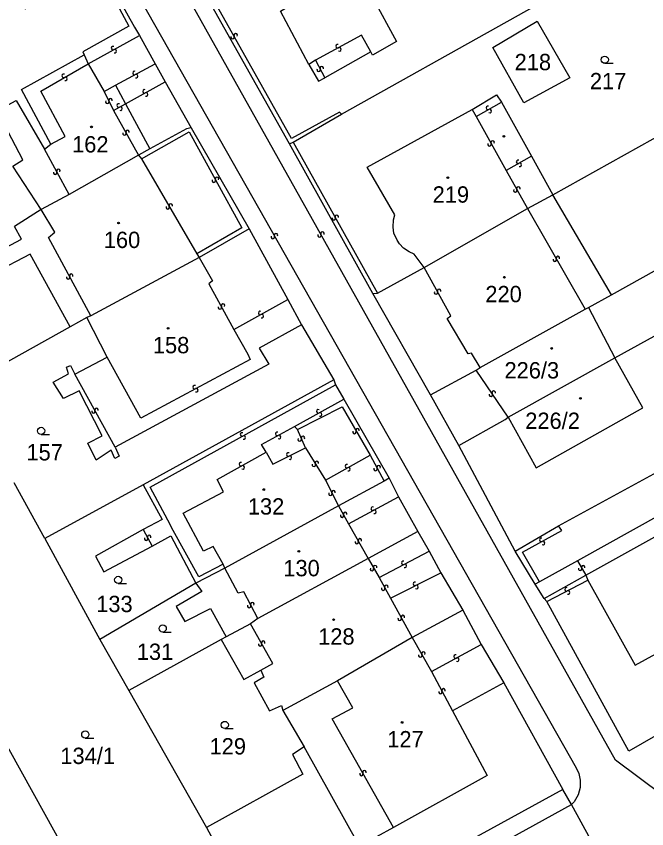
# Model space of a CAD drawing. Extents: x -600391 to -599491, y -1160176 to -1159402.
# Drawn here: x -600329.6 to -600264, y -1159832 to -1159747.5 of the extents above; entities that cross this region are included whole.
import ezdxf

# ---------------------------------------------------------------- set-up
doc = ezdxf.new("R2010")
doc.units = 0
for name, color, linetype in [('Level 1', 7, 'Continuous'), ('Level 13', 7, 'Continuous'), ('Level 3', 7, 'Continuous'), ('Level 4', 7, 'Continuous'), ('Level 5', 7, 'Continuous')]:
    doc.layers.add(name, color=color, linetype=linetype)

msp = doc.modelspace()

# ---------------------------------------------------------------- linework, layer by layer
at = {"layer": 'Level 1'}
for points in [[(-600299.17, -1159752.49), (-600302.11, -1159746.96), (-600301.17, -1159746.41), (-600303.61, -1159741.8), (-600292.85, -1159735.57), (-600288.77, -1159743.19), (-600292.56, -1159745.42), (-600290.03, -1159750.12), (-600292.55, -1159751.52), (-600292.72, -1159751.2)], [(-600295.75, -1159757.68), (-600261.29, -1159738.36)], [(-600301.19, -1159760.77), (-600313.32, -1159739.14)], [(-600320.77, -1159741.86), (-600320.81, -1159742.32), (-600317.3, -1159748.63), (-600316.77, -1159749.5)], [(-600280.02, -1159750.72), (-600275.38, -1159747.98), (-600271.99, -1159753.9), (-600276.77, -1159756.5), (-600280.02, -1159750.72)], [(-600316.77, -1159749.5), (-600315.17, -1159752.43)], [(-600292.72, -1159751.2), (-600297.48, -1159753.88)], [(-600326.01, -1159760.79), (-600329.08, -1159755.1), (-600322.55, -1159751.51)], [(-600322.55, -1159751.51), (-600322.12, -1159752.43)], [(-600322.12, -1159752.43), (-600320.45, -1159755.32)], [(-600315.17, -1159752.43), (-600314.12, -1159754.32)], [(-600299.17, -1159752.49), (-600298.16, -1159754.23), (-600297.48, -1159753.88)], [(-600320.45, -1159755.32), (-600319.27, -1159754.67)], [(-600319.27, -1159754.67), (-600318.23, -1159756.59)], [(-600314.12, -1159754.32), (-600311.4, -1159759.11)], [(-600273.75, -1159766.05), (-600252.87, -1159754.41)], [(-600327.03, -1159767.58), (-600329.98, -1159763.08), (-600328.92, -1159762.44), (-600331.62, -1159757.33), (-600329.63, -1159756.26), (-600326.67, -1159761.32)], [(-600282.17, -1159757.17), (-600279.61, -1159755.67), (-600279.11, -1159756.44)], [(-600318.23, -1159756.59), (-600315.71, -1159761.28)], [(-600287.15, -1159773.61), (-600288.19, -1159772.24), (-600288.73, -1159772), (-600289.31, -1159771.61), (-600289.72, -1159771.17), (-600289.98, -1159770.79), (-600290.3, -1159770.07), (-600290.39, -1159769.43), (-600290.35, -1159768.68), (-600290.22, -1159768.16), (-600293.08, -1159763.17), (-600282.17, -1159757.17)], [(-600279.11, -1159756.44), (-600275.97, -1159762.05)], [(-600300.8, -1159760.59), (-600295.75, -1159757.68)], [(-600311.4, -1159759.11), (-600311.9, -1159759.19), (-600315.71, -1159761.28)], [(-600311.4, -1159759.11), (-600305.38, -1159769.61)], [(-600301.19, -1159760.77), (-600300.8, -1159760.59)], [(-600326.67, -1159761.32), (-600326.01, -1159760.79)], [(-600315.71, -1159761.28), (-600316.89, -1159761.93)], [(-600292.5, -1159776.32), (-600301.19, -1159760.77)], [(-600316.89, -1159761.93), (-600324.12, -1159766.04)], [(-600275.97, -1159762.05), (-600273.75, -1159766.05)], [(-600267.66, -1159776.47), (-600247.31, -1159765.14)], [(-600324.12, -1159766.04), (-600327.03, -1159767.58)], [(-600276.4, -1159767.49), (-600273.75, -1159766.05)], [(-600267.66, -1159776.47), (-600273.75, -1159766.05)], [(-600327.03, -1159767.58), (-600329.78, -1159769.35)], [(-600287.15, -1159773.61), (-600276.4, -1159767.49)], [(-600324, -1159779.81), (-600328.15, -1159772.25), (-600331.92, -1159774.18), (-600332.83, -1159772.65), (-600329.08, -1159770.69), (-600329.78, -1159769.35)], [(-600305.38, -1159769.61), (-600310.58, -1159772.6)], [(-600305.38, -1159769.61), (-600301.33, -1159776.97)], [(-600267.31, -1159783.02), (-600244.51, -1159770.47)], [(-600310.58, -1159772.6), (-600321.85, -1159778.65)], [(-600292.02, -1159776.29), (-600287.15, -1159773.61)], [(-600292.5, -1159776.32), (-600292.02, -1159776.29)], [(-600286.5, -1159786.86), (-600292.5, -1159776.32)], [(-600270.06, -1159777.8), (-600267.66, -1159776.47)], [(-600301.33, -1159776.97), (-600299.92, -1159779.6)], [(-600281.32, -1159784.02), (-600270.4, -1159777.96)], [(-600270.4, -1159777.96), (-600270.06, -1159777.8)], [(-600270.06, -1159777.8), (-600267.31, -1159783.02)], [(-600322.27, -1159778.82), (-600324, -1159779.81)], [(-600321.85, -1159778.65), (-600322.27, -1159778.82)], [(-600320.14, -1159782.97), (-600322.27, -1159778.82)], [(-600324, -1159779.81), (-600335.29, -1159786.07)], [(-600299.92, -1159779.6), (-600304.33, -1159782.01), (-600303.34, -1159783.68), (-600319.31, -1159792.32)], [(-600299.92, -1159779.6), (-600296.57, -1159785.31)], [(-600323.53, -1159784.71), (-600320.14, -1159782.97)], [(-600278.4, -1159789.21), (-600275.51, -1159794.48), (-600264.4, -1159788.24), (-600267.31, -1159783.02)], [(-600278.4, -1159789.21), (-600267.31, -1159783.02)], [(-600273.16, -1159800.51), (-600241.13, -1159783.01)], [(-600319.31, -1159792.32), (-600318.91, -1159793.25), (-600319.34, -1159793.5), (-600319.72, -1159792.63), (-600321.3, -1159793.68), (-600322.18, -1159791.89), (-600320.68, -1159791.13), (-600323.08, -1159786.45), (-600324.68, -1159787.25), (-600325.77, -1159785.54), (-600324.16, -1159784.69), (-600324.38, -1159783.99), (-600323.98, -1159783.83), (-600323.53, -1159784.71)], [(-600281.75, -1159784.3), (-600281.32, -1159784.02)], [(-600286.5, -1159786.86), (-600281.75, -1159784.3)], [(-600296.57, -1159785.31), (-600316.42, -1159796.25)], [(-600296.57, -1159785.31), (-600296.39, -1159785.82)], [(-600296.39, -1159785.82), (-600295.53, -1159787.33)], [(-600295.53, -1159787.33), (-600290.8, -1159795.55)], [(-600283.56, -1159792.14), (-600286.5, -1159786.86)], [(-600283.56, -1159792.14), (-600278.72, -1159789.43), (-600278.4, -1159789.21)], [(-600241.63, -1159801.92), (-600247.72, -1159791.06), (-600271.19, -1159804.13)], [(-600277.68, -1159803.12), (-600283.56, -1159792.14)], [(-600326.65, -1159801.81), (-600329.83, -1159796.03)], [(-600291.31, -1159795.84), (-600296.06, -1159798.41)], [(-600290.8, -1159795.55), (-600291.31, -1159795.84)], [(-600290.8, -1159795.55), (-600289.82, -1159797.47)], [(-600316.42, -1159796.25), (-600326.65, -1159801.81)], [(-600316.42, -1159796.25), (-600314.44, -1159799.83), (-600316.4, -1159800.89)], [(-600289.82, -1159797.47), (-600287.82, -1159801.08)], [(-600296.06, -1159798.41), (-600307.89, -1159804.92)], [(-600316.4, -1159800.89), (-600321.35, -1159803.66), (-600320.51, -1159805.27), (-600315.47, -1159802.6)], [(-600287.82, -1159801.08), (-600293, -1159803.9)], [(-600287.82, -1159801.08), (-600286.65, -1159803.15)], [(-600277.68, -1159803.12), (-600273.16, -1159800.51)], [(-600326.65, -1159801.81), (-600320.92, -1159812.34)], [(-600315.47, -1159802.6), (-600313.53, -1159801.55), (-600310.91, -1159806.45)], [(-600342.05, -1159802.75), (-600323.23, -1159836.65)], [(-600286.65, -1159803.15), (-600285.43, -1159805.38)], [(-600275.6, -1159806.57), (-600277.68, -1159803.12)], [(-600293, -1159803.9), (-600304.47, -1159810.14)], [(-600271.19, -1159804.13), (-600275.14, -1159806.32)], [(-600307.89, -1159804.92), (-600310.91, -1159806.45)], [(-600285.43, -1159805.38), (-600283.13, -1159809.27)], [(-600274.67, -1159808.06), (-600270.34, -1159805.64)], [(-600270.34, -1159805.64), (-600270.12, -1159806.15)], [(-600270.12, -1159806.15), (-600265.18, -1159814.99), (-600256.58, -1159810.28)], [(-600310.91, -1159806.45), (-600320.92, -1159812.34)], [(-600310.91, -1159806.45), (-600310.3, -1159807.33), (-600312.97, -1159808.88), (-600312.07, -1159810.44), (-600309.38, -1159809.09), (-600307.76, -1159812.05)], [(-600275.14, -1159806.32), (-600275.6, -1159806.57)], [(-600274.67, -1159808.06), (-600275.6, -1159806.57)], [(-600274.4, -1159808.39), (-600274.67, -1159808.06)], [(-600261.69, -1159821.56), (-600265.84, -1159823.95), (-600274.4, -1159808.39)], [(-600283.13, -1159809.27), (-600288.42, -1159812.13)], [(-600283.13, -1159809.27), (-600281.21, -1159812.86)], [(-600304.47, -1159810.14), (-600305.23, -1159810.68)], [(-600305.23, -1159810.68), (-600307.76, -1159812.05)], [(-600307.76, -1159812.05), (-600308.27, -1159812.32)], [(-600288.42, -1159812.13), (-600296.16, -1159816.64)], [(-600320.92, -1159812.34), (-600317.91, -1159817.64)], [(-600308.27, -1159812.32), (-600317.91, -1159817.64)], [(-600308.27, -1159812.32), (-600305.91, -1159816.49), (-600304.16, -1159815.51)], [(-600281.21, -1159812.86), (-600278.88, -1159816.85)], [(-600304.16, -1159815.51), (-600303.84, -1159816.23), (-600304.86, -1159816.84), (-600303.27, -1159819.76), (-600302.02, -1159819.18), (-600301.85, -1159819.73)], [(-600296.16, -1159816.64), (-600301.85, -1159819.73)], [(-600278.88, -1159816.85), (-600284.2, -1159819.76)], [(-600278.88, -1159816.85), (-600272.73, -1159827.94)], [(-600317.91, -1159817.64), (-600309.8, -1159831.89)], [(-600301.85, -1159819.73), (-600299.65, -1159823.5)], [(-600284.2, -1159819.76), (-600280.6, -1159826.47), (-600290.35, -1159831.88)], [(-600299.65, -1159823.5), (-600300.87, -1159824.29), (-600299.8, -1159826.35), (-600309.8, -1159831.89)], [(-600290.35, -1159831.88), (-600293.9, -1159833.81), (-600299.65, -1159823.5)], [(-600272.73, -1159827.94), (-600300.01, -1159842.88)], [(-600271.82, -1159829.5), (-600272.73, -1159827.94)], [(-600268.81, -1159835), (-600271.82, -1159829.5)], [(-600309.8, -1159831.89), (-600305.26, -1159840.26)]]:
    msp.add_lwpolyline(points, dxfattribs=at)
at = {"layer": 'Level 13'}
for centre, start, end in [((-600307.102, -1159749.659), 156.69209, 28.79008), ((-600306.779, -1159749.481), 336.47763, 209.06763), ((-600296.167, -1159750.598), 65.46617, 298.05617), ((-600319.537, -1159750.797), 66.08065, 298.17864), ((-600319.362, -1159751.122), 245.86619, 118.45619), ((-600295.994, -1159750.923), 245.68062, 117.77862), ((-600298.142, -1159753.058), 155.81259, 28.40259), ((-600297.817, -1159752.883), 336.02705, 208.12504), ((-600324.671, -1159753.689), 67.36781, 299.46581), ((-600324.489, -1159754.01), 247.15336, 119.74336), ((-600317.307, -1159753.387), 66.02234, 298.12034), ((-600317.132, -1159753.712), 245.80789, 118.39789), ((-600316.268, -1159755.298), 66.28511, 298.3831), ((-600316.092, -1159755.622), 246.07065, 118.66065), ((-600320.135, -1159756.381), 153.48899, 26.07899), ((-600319.804, -1159756.22), 333.70345, 205.80144), ((-600318.948, -1159756.778), 66.27143, 298.36943), ((-600318.772, -1159757.102), 246.05697, 118.64698), ((-600280.519, -1159757.018), 66.64799, 298.74598), ((-600280.341, -1159757.341), 246.43353, 119.02353), ((-600318.351, -1159759.689), 156.27561, 28.86561), ((-600318.028, -1159759.512), 336.49007, 208.58807), ((-600280.028, -1159760.632), 336.57481, 208.6728), ((-600280.351, -1159760.809), 156.36035, 28.95035), ((-600277.379, -1159762.629), 66.17615, 298.76615), ((-600277.202, -1159762.952), 246.39061, 118.48861), ((-600325.563, -1159763.766), 155.75306, 27.85105), ((-600325.238, -1159763.593), 335.5386, 208.1286), ((-600309.042, -1159764.588), 155.99774, 28.58774), ((-600308.718, -1159764.413), 336.2122, 208.31019), ((-600277.671, -1159765.589), 156.37193, 28.96193), ((-600277.348, -1159765.411), 336.58639, 208.68439), ((-600313.849, -1159767.362), 157.42554, 30.01554), ((-600313.53, -1159767.179), 337.64, 209.73799), ((-600296.248, -1159768.351), 336.58821, 208.68621), ((-600296.571, -1159768.529), 156.37376, 28.96376), ((-600302.9, -1159770.45), 156.74056, 29.33056), ((-600302.579, -1159770.27), 336.95502, 209.05302), ((-600298.062, -1159770.279), 156.64787, 28.74586), ((-600297.739, -1159770.101), 336.43341, 209.02341), ((-600273.56, -1159772.821), 156.97383, 29.56383), ((-600273.239, -1159772.64), 337.18828, 209.28628), ((-600324.213, -1159774.656), 155.76135, 27.85934), ((-600323.888, -1159774.483), 335.54689, 208.13689), ((-600285.922, -1159776.227), 156.2053, 28.3033), ((-600285.598, -1159776.052), 335.99084, 208.58084), ((-600308.097, -1159777.603), 336.10954, 208.20754), ((-600308.422, -1159777.778), 155.89509, 28.48509), ((-600304.228, -1159778.358), 66.25393, 298.35192), ((-600304.052, -1159778.682), 246.03947, 118.62947), ((-600311.046, -1159786.067), 65.41093, 298.00093), ((-600310.874, -1159786.393), 245.62539, 117.72338), ((-600280.223, -1159786.853), 161.67771, 33.77571), ((-600279.918, -1159786.647), 341.46326, 214.05326), ((-600321.259, -1159788.431), 336.16811, 208.75811), ((-600298.168, -1159788.588), 66.35112, 298.44912), ((-600321.582, -1159788.608), 156.38257, 28.48057), ((-600297.992, -1159788.911), 246.13666, 118.72666), ((-600306.108, -1159790.998), 66.34649, 298.44449), ((-600302.447, -1159790.938), 66.15794, 298.25594), ((-600294.41, -1159790.731), 157.11044, 29.70044), ((-600294.089, -1159790.549), 337.3249, 209.42289), ((-600305.932, -1159791.321), 246.13203, 118.72203), ((-600302.272, -1159791.262), 245.94349, 118.53349), ((-600300.11, -1159791.513), 151.08158, 23.17958), ((-600299.771, -1159791.367), 330.86712, 203.45712), ((-600301.302, -1159793.075), 64.27481, 296.37281), ((-600301.137, -1159793.405), 244.06036, 116.65036), ((-600306.228, -1159794.088), 66.43686, 298.53485), ((-600306.051, -1159794.411), 246.2224, 118.8124), ((-600298.637, -1159794.156), 158.91776, 31.50776), ((-600298.322, -1159793.964), 339.13221, 211.23021), ((-600295.208, -1159794.288), 66.39594, 298.49394), ((-600291.888, -1159794.412), 336.28192, 208.37991), ((-600295.031, -1159794.611), 246.18149, 118.77149), ((-600292.212, -1159794.588), 156.06746, 28.65746), ((-600296.585, -1159796.997), 334.70509, 206.80309), ((-600296.914, -1159797.164), 154.49064, 27.08064), ((-600292.506, -1159798.717), 65.84405, 297.94205), ((-600295.701, -1159799.438), 156.10927, 28.69927), ((-600295.378, -1159799.262), 336.32373, 208.42173), ((-600292.333, -1159799.042), 245.62959, 118.21959), ((-600316.102, -1159801.837), 155.69826, 28.28826), ((-600315.777, -1159801.663), 335.91272, 208.01072), ((-600293.848, -1159802.011), 336.60223, 208.70022), ((-600274.967, -1159801.957), 65.96366, 298.06165), ((-600294.171, -1159802.189), 156.38777, 28.97777), ((-600274.793, -1159802.282), 245.7492, 118.3392), ((-600289.334, -1159804.346), 64.98576, 297.08376), ((-600289.165, -1159804.673), 244.77131, 117.36131), ((-600292.589, -1159804.982), 157.43279, 30.02279), ((-600292.27, -1159804.798), 337.64725, 209.74525), ((-600270.921, -1159804.98), 156.53404, 29.12404), ((-600270.598, -1159804.801), 336.7485, 208.8465), ((-600291.421, -1159807.028), 156.1223, 28.7123), ((-600291.098, -1159806.852), 336.33675, 208.43475), ((-600288.132, -1159806.535), 64.15647, 296.25447), ((-600287.968, -1159806.865), 243.94201, 116.53201), ((-600272.344, -1159807.106), 64.9987, 297.09669), ((-600272.175, -1159807.433), 244.78424, 117.37424), ((-600305.364, -1159808.834), 155.08028, 27.17828), ((-600305.037, -1159808.665), 334.86583, 207.45583), ((-600289.702, -1159810.167), 155.7492, 28.3392), ((-600289.377, -1159809.993), 335.96366, 208.06165), ((-600304.232, -1159812.838), 156.53298, 28.63098), ((-600303.909, -1159812.661), 336.31853, 208.90853), ((-600287.239, -1159813.81), 337.27468, 209.37268), ((-600287.56, -1159813.991), 157.06023, 29.65023), ((-600283.886, -1159814.097), 65.76575, 297.86375), ((-600283.713, -1159814.422), 245.5513, 118.1413), ((-600285.463, -1159817.796), 155.26702, 27.85702), ((-600285.137, -1159817.625), 335.48148, 207.57947), ((-600293.692, -1159826.319), 156.76174, 28.85974), ((-600293.369, -1159826.14), 336.54729, 209.13729)]:
    msp.add_arc(centre, 0.184, start, end, dxfattribs=at)
at = {"layer": 'Level 3'}
for points in [[(-600230.31, -1159867.23), (-600234.28, -1159869.41), (-600235.16, -1159869.58), (-600236.07, -1159869.58), (-600236.89, -1159869.39), (-600237.73, -1159869.01), (-600238.36, -1159868.54), (-600238.85, -1159868.03), (-600259.85, -1159830.4), (-600267.23, -1159824.89), (-600328.56, -1159715.49), (-600329.16, -1159714.44), (-600329.45, -1159713.11), (-600329.33, -1159711.96), (-600329.03, -1159711.13)], [(-600336.94, -1159712.9), (-600335.74, -1159713.51), (-600334.73, -1159714.36), (-600334.14, -1159715.06), (-600271.35, -1159825.67), (-600271.05, -1159826.26), (-600270.91, -1159826.95), (-600270.93, -1159827.71), (-600271.14, -1159828.5), (-600271.56, -1159829.2), (-600271.82, -1159829.5)], [(-600295.75, -1159757.68), (-600295.96, -1159757.47), (-600300.97, -1159760.2), (-600312.91, -1159738.94)], [(-600328.85, -1159746.29), (-600328.68, -1159746.7), (-600321.12, -1159742.5), (-600317.89, -1159748.53), (-600322.7, -1159751.2), (-600322.55, -1159751.51)], [(-600322.12, -1159752.43), (-600316.77, -1159749.5)], [(-600292.72, -1159751.2), (-600293.69, -1159749.47), (-600298.48, -1159752.05)], [(-600298.48, -1159752.05), (-600299.17, -1159752.49)], [(-600298.48, -1159752.05), (-600297.48, -1159753.88)], [(-600326.01, -1159760.79), (-600324.51, -1159759.99), (-600327.04, -1159755.27), (-600322.12, -1159752.43)], [(-600319.27, -1159754.67), (-600315.17, -1159752.43)], [(-600318.23, -1159756.59), (-600314.12, -1159754.32)], [(-600320.45, -1159755.32), (-600319.48, -1159757.28)], [(-600319.48, -1159757.28), (-600318.23, -1159756.59)], [(-600282.17, -1159757.17), (-600281.75, -1159757.92)], [(-600281.75, -1159757.92), (-600279.11, -1159756.44)], [(-600319.48, -1159757.28), (-600316.89, -1159761.93)], [(-600281.75, -1159757.92), (-600278.62, -1159763.52)], [(-600316.57, -1159762.33), (-600311.63, -1159759.52), (-600306.14, -1159769.49), (-600310.81, -1159772.2)], [(-600300.8, -1159760.59), (-600292.02, -1159776.29)], [(-600324.12, -1159766.04), (-600326.67, -1159761.32)], [(-600316.89, -1159761.93), (-600316.57, -1159762.33)], [(-600275.97, -1159762.05), (-600278.62, -1159763.52)], [(-600316.57, -1159762.33), (-600310.81, -1159772.2)], [(-600278.62, -1159763.52), (-600276.4, -1159767.49)], [(-600321.85, -1159778.65), (-600326.26, -1159770.49), (-600325.6, -1159769.96), (-600327.03, -1159767.58)], [(-600276.4, -1159767.49), (-600270.4, -1159777.96)], [(-600310.81, -1159772.2), (-600310.58, -1159772.6)], [(-600310.58, -1159772.6), (-600309.2, -1159775), (-600309.56, -1159775.31), (-600306.95, -1159780.07)], [(-600281.32, -1159784.02), (-600282.23, -1159782.53), (-600282.59, -1159782.61), (-600284.75, -1159778.94), (-600284.37, -1159778.66), (-600287.15, -1159773.61)], [(-600306.95, -1159780.07), (-600301.33, -1159776.97)], [(-600306.95, -1159780.07), (-600305.51, -1159782.63), (-600305.27, -1159783.18), (-600316.64, -1159789.29), (-600320.14, -1159782.97)], [(-600319.31, -1159792.32), (-600323.53, -1159784.71)], [(-600278.4, -1159789.21), (-600281.75, -1159784.3)], [(-600308.09, -1159804.49), (-600310.61, -1159805.81), (-600313.29, -1159800.97), (-600313.85, -1159799.9), (-600315.66, -1159796.49), (-600296.39, -1159785.82)], [(-600300.64, -1159790.16), (-600295.53, -1159787.33)], [(-600300.35, -1159790.49), (-600295.7, -1159788.11), (-600292.79, -1159793.16)], [(-600303.59, -1159792.83), (-600304.08, -1159792.05), (-600300.64, -1159790.16)], [(-600300.35, -1159790.49), (-600300.64, -1159790.16)], [(-600299.52, -1159792.38), (-600300.35, -1159790.49)], [(-600303.59, -1159792.83), (-600302.91, -1159794.1), (-600299.52, -1159792.38)], [(-600299.52, -1159792.38), (-600297.44, -1159795.74)], [(-600308.09, -1159804.49), (-600309.13, -1159802.66), (-600310.12, -1159803.15), (-600312.23, -1159799.2), (-600308.05, -1159796.95), (-600308.7, -1159795.67), (-600303.59, -1159792.83)], [(-600297.44, -1159795.74), (-600292.79, -1159793.16)], [(-600292.79, -1159793.16), (-600291.31, -1159795.84)], [(-600270.34, -1159805.64), (-600248.4, -1159793.47), (-600243.17, -1159802.85)], [(-600297.44, -1159795.74), (-600296.06, -1159798.41)], [(-600295.02, -1159800.29), (-600289.82, -1159797.47)], [(-600296.06, -1159798.41), (-600295.02, -1159800.29)], [(-600295.02, -1159800.29), (-600293, -1159803.9)], [(-600316.4, -1159800.89), (-600315.47, -1159802.6)], [(-600275.14, -1159806.32), (-600276.93, -1159803.24), (-600272.82, -1159801), (-600273.16, -1159800.51)], [(-600291.85, -1159805.87), (-600286.65, -1159803.15)], [(-600307.89, -1159804.92), (-600308.09, -1159804.49)], [(-600293, -1159803.9), (-600291.85, -1159805.87)], [(-600271.19, -1159804.13), (-600270.34, -1159805.64)], [(-600304.47, -1159810.14), (-600305.93, -1159807.36), (-600306.5, -1159807.52), (-600307.89, -1159804.92)], [(-600290.66, -1159808.02), (-600285.43, -1159805.38)], [(-600291.85, -1159805.87), (-600290.66, -1159808.02)], [(-600274.4, -1159808.39), (-600270.12, -1159806.15)], [(-600290.66, -1159808.02), (-600288.42, -1159812.13)], [(-600304.16, -1159815.51), (-600302.92, -1159814.82), (-600305.23, -1159810.68)], [(-600288.42, -1159812.13), (-600286.39, -1159815.66)], [(-600286.39, -1159815.66), (-600281.21, -1159812.86)], [(-600286.39, -1159815.66), (-600284.2, -1159819.76)], [(-600290.35, -1159831.88), (-600296.72, -1159820.57), (-600294.57, -1159819.44), (-600296.16, -1159816.64)], [(-600373.95, -1159885.79), (-600271.82, -1159829.5)]]:
    msp.add_lwpolyline(points, dxfattribs=at)
at = {"layer": 'Level 5'}
for p, q in [((-600268.36, -1159752.38), (-600267.485, -1159752.38)), ((-600327.03, -1159791), (-600326.155, -1159791)), ((-600319, -1159806.5), (-600318.125, -1159806.5)), ((-600314.37, -1159811.55), (-600313.495, -1159811.55)), ((-600307.91, -1159821.59), (-600307.035, -1159821.59)), ((-600322.43, -1159822.58), (-600321.555, -1159822.58))]:
    msp.add_line(p, q, dxfattribs=at)
for centre, radius in [((-600268.36, -1159752.005), 0.375), ((-600321.78, -1159759), 0.09), ((-600321.78, -1159759), 0.0521), ((-600278.86, -1159759.98), 0.09), ((-600278.86, -1159759.98), 0.0521), ((-600284.69, -1159764.28), 0.09), ((-600284.69, -1159764.28), 0.0521), ((-600318.96, -1159769), 0.09), ((-600318.96, -1159769), 0.0521), ((-600278.81, -1159774.64), 0.09), ((-600278.81, -1159774.64), 0.0521), ((-600313.81, -1159779.95), 0.09), ((-600313.81, -1159779.95), 0.0521), ((-600273.88, -1159782.04), 0.09), ((-600273.88, -1159782.04), 0.0521), ((-600270.89, -1159787.24), 0.09), ((-600270.89, -1159787.24), 0.0521), ((-600327.03, -1159790.625), 0.375), ((-600303.85, -1159796.73), 0.09), ((-600303.85, -1159796.73), 0.0521), ((-600300.2, -1159803.15), 0.09), ((-600300.2, -1159803.15), 0.0521), ((-600319, -1159806.125), 0.375), ((-600296.58, -1159810.26), 0.09), ((-600296.58, -1159810.26), 0.0521), ((-600314.37, -1159811.175), 0.375), ((-600307.91, -1159821.215), 0.375), ((-600289.45, -1159820.95), 0.09), ((-600289.45, -1159820.95), 0.0521), ((-600322.43, -1159822.205), 0.375)]:
    msp.add_circle(centre, radius, dxfattribs=at)

# ---------------------------------------------------------------- texts
at = {"layer": 'Level 4'}
for s, p in [('218', (-600277.74, -1159753.1)), ('217', (-600269.907, -1159755.08)), ('162', (-600323.802, -1159761.66)), ('219', (-600286.272, -1159766.88)), ('160', (-600320.501, -1159771.6)), ('220', (-600280.788, -1159777.24)), ('158', (-600315.396, -1159782.55)), ('226/3', (-600278.796, -1159785.17)), ('226/2', (-600276.634, -1159790.42)), ('157', (-600328.553, -1159793.7)), ('132', (-600305.509, -1159799.33)), ('130', (-600301.818, -1159805.75)), ('133', (-600321.291, -1159809.48)), ('128', (-600298.19, -1159812.86)), ('131', (-600317.067, -1159814.45)), ('127', (-600290.997, -1159823.55)), ('129', (-600309.492, -1159824.29)), ('134/1', (-600325.022, -1159825.28))]:
    msp.add_text(s, height=1.7, dxfattribs=at).set_placement(p)

doc.saveas('drawing.dxf')
